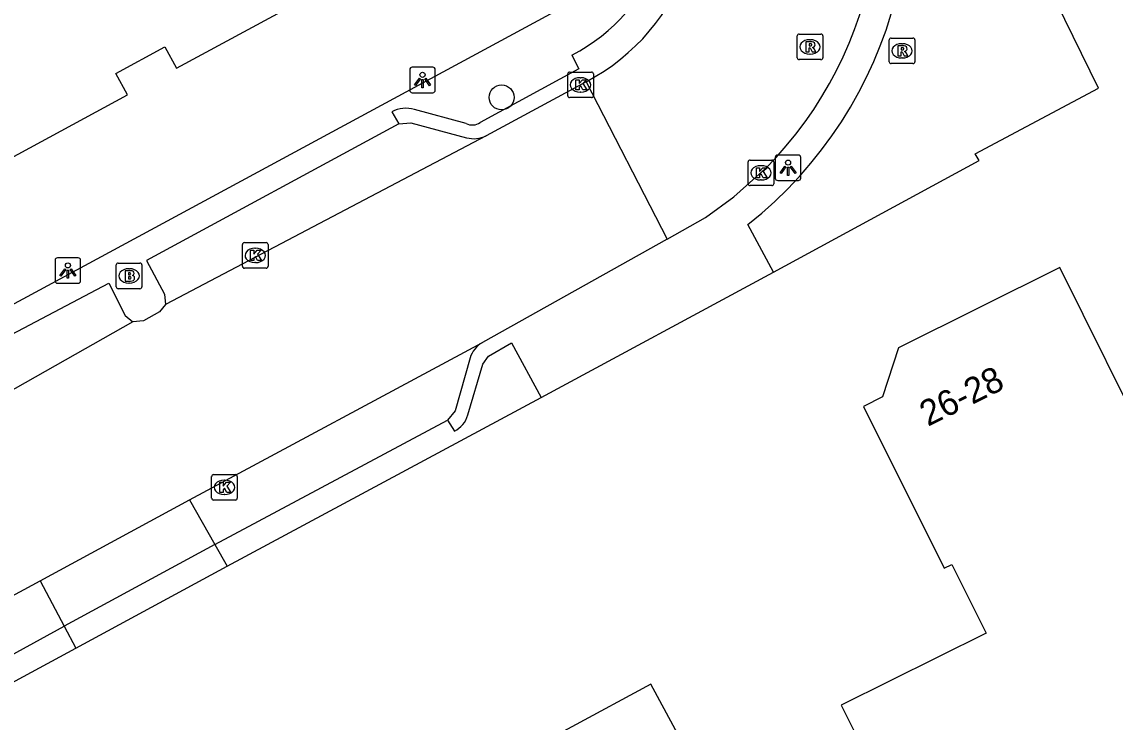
# Model space of a CAD drawing. Extents: x 158461 to 159795, y 387220 to 388672.
# Drawn here: x 158920.02 to 158962.78, y 387554.14 to 387581.53 of the extents above; entities that cross this region are included whole.
import ezdxf

# ---------------------------------------------------------------- set-up
doc = ezdxf.new("R2010")
doc.units = 0
for name, color, linetype in [('IMGEO_Boom', 7, 'Continuous'), ('IMGEO_Brandkraan', 7, 'Continuous'), ('IMGEO_Kolk', 7, 'Continuous'), ('IMGEO_Lichtpunt', 7, 'Continuous'), ('IMGEO_Pand', 7, 'Continuous'), ('IMGEO_Pand_nummerreeks', 7, 'Continuous'), ('IMGEO_Rijbaan_lokaal_gesloten', 7, 'Continuous'), ('IMGEO_Rioolput', 7, 'Continuous'), ('IMGEO_Voetpad_open', 7, 'Continuous')]:
    doc.layers.add(name, color=color, linetype=linetype)

msp = doc.modelspace()

# ---------------------------------------------------------------- linework, layer by layer
at = {"layer": 'IMGEO_Boom'}
msp.add_circle((158938.784, 387578.571), 0.489, dxfattribs=at)
at = {"layer": 'IMGEO_Brandkraan'}
for p, q in [((158923.79, 387572.09), (158924.642, 387572.09)), ((158923.715, 387571.164), (158923.715, 387572.016)), ((158924.203, 387571.87), (158924.228, 387571.87)), ((158924.716, 387572.016), (158924.716, 387571.164)), ((158924.226, 387571.31), (158924.201, 387571.31)), ((158924.642, 387571.09), (158923.79, 387571.09))]:
    msp.add_line(p, q, dxfattribs=at)
for points in [[(158923.79, 387572.09), (158924.642, 387572.09)], [(158923.715, 387571.164), (158923.715, 387572.016)], [(158924.063, 387571.79), (158924.063, 387571.39), (158924.276, 387571.39)], [(158924.294, 387571.79), (158924.063, 387571.79)], [(158924.242, 387571.709), (158924.188, 387571.709), (158924.188, 387571.633)], [(158924.716, 387572.016), (158924.716, 387571.164)], [(158924.188, 387571.633), (158924.241, 387571.633)], [(158924.25, 387571.557), (158924.188, 387571.557), (158924.188, 387571.476)], [(158924.188, 387571.476), (158924.25, 387571.476)], [(158924.642, 387571.09), (158923.79, 387571.09)]]:
    msp.add_lwpolyline(points, dxfattribs=at)
for centre, radius, start, end in [((158923.792, 387572.014), 0.0765, 91.552, 178.448), ((158923.792, 387572.014), 0.0765, 91.552, 178.448), ((158924.64, 387572.014), 0.0765, 1.552, 88.448), ((158924.64, 387572.014), 0.0765, 1.552, 88.448), ((158924.243, 387571.671), 0.0379, 267.8285, 90.9355), ((158924.298, 387571.645), 0.145, 59.4692, 91.5367), ((158924.323, 387571.692), 0.0922, 285.5137, 58.1501), ((158924.251, 387571.516), 0.0404, 269.8759, 90.5077), ((158924.282, 387571.641), 0.251, 268.6676, 293.5347), ((158924.328, 387571.5), 0.105, 301.3115, 78.989), ((158923.792, 387571.166), 0.0765, 181.552, 268.448), ((158923.792, 387571.166), 0.0765, 181.552, 268.448), ((158924.64, 387571.166), 0.0765, 271.552, 358.448), ((158924.64, 387571.166), 0.0765, 271.552, 358.448)]:
    msp.add_arc(centre, radius, start, end, dxfattribs=at)
for centre, major_axis, ratio, start_param, end_param in [((158924.202, 387571.59), (-0.387, 0.002), 0.722429, 4.712389, 7.853982), ((158924.227, 387571.59), (-0.39, 0.002), 0.717154, 1.570796, 4.712389)]:
    msp.add_ellipse(centre, major_axis=major_axis, ratio=ratio, start_param=start_param, end_param=end_param, dxfattribs=at)
at = {"layer": 'IMGEO_Kolk'}
for p, q in [((158941.371, 387578.635), (158941.371, 387579.487)), ((158941.446, 387579.561), (158942.298, 387579.561)), ((158942.372, 387579.487), (158942.372, 387578.635)), ((158941.859, 387579.341), (158941.884, 387579.341)), ((158942.298, 387578.561), (158941.446, 387578.561)), ((158941.882, 387578.781), (158941.857, 387578.781)), ((158948.426, 387575.195), (158948.426, 387576.047)), ((158948.501, 387576.121), (158949.353, 387576.121)), ((158949.427, 387576.047), (158949.427, 387575.195)), ((158948.914, 387575.901), (158948.939, 387575.901)), ((158949.353, 387575.121), (158948.501, 387575.121)), ((158948.937, 387575.341), (158948.912, 387575.341)), ((158928.649, 387571.964), (158928.649, 387572.816)), ((158928.724, 387572.89), (158929.576, 387572.89)), ((158929.137, 387572.67), (158929.162, 387572.67)), ((158929.65, 387572.816), (158929.65, 387571.964)), ((158929.16, 387572.11), (158929.135, 387572.11)), ((158929.576, 387571.89), (158928.724, 387571.89)), ((158927.445, 387562.895), (158927.445, 387563.747)), ((158927.52, 387563.821), (158928.372, 387563.821)), ((158927.933, 387563.601), (158927.958, 387563.601)), ((158928.446, 387563.747), (158928.446, 387562.895)), ((158928.372, 387562.821), (158927.52, 387562.821)), ((158927.956, 387563.041), (158927.931, 387563.041))]:
    msp.add_line(p, q, dxfattribs=at)
for points in [[(158941.371, 387578.635), (158941.371, 387579.487)], [(158941.446, 387579.561), (158942.298, 387579.561)], [(158942.372, 387579.487), (158942.372, 387578.635)], [(158941.692, 387579.261), (158941.815, 387579.261), (158941.815, 387579.11), (158941.945, 387579.261), (158942.109, 387579.261), (158941.963, 387579.11), (158942.116, 387578.861), (158941.964, 387578.861), (158941.879, 387579.025), (158941.815, 387578.958), (158941.815, 387578.861), (158941.692, 387578.861), (158941.692, 387579.261)], [(158942.298, 387578.561), (158941.446, 387578.561)], [(158948.426, 387575.195), (158948.426, 387576.047)], [(158948.501, 387576.121), (158949.353, 387576.121)], [(158949.427, 387576.047), (158949.427, 387575.195)], [(158948.747, 387575.821), (158948.87, 387575.821), (158948.87, 387575.67), (158949, 387575.821), (158949.164, 387575.821), (158949.018, 387575.67), (158949.171, 387575.421), (158949.019, 387575.421), (158948.934, 387575.585), (158948.87, 387575.518), (158948.87, 387575.421), (158948.747, 387575.421), (158948.747, 387575.821)], [(158949.353, 387575.121), (158948.501, 387575.121)], [(158928.649, 387571.964), (158928.649, 387572.816)], [(158928.724, 387572.89), (158929.576, 387572.89)], [(158928.97, 387572.59), (158929.093, 387572.59), (158929.093, 387572.439), (158929.223, 387572.59), (158929.387, 387572.59), (158929.241, 387572.439), (158929.394, 387572.19), (158929.242, 387572.19), (158929.157, 387572.354), (158929.093, 387572.287), (158929.093, 387572.19), (158928.97, 387572.19), (158928.97, 387572.59)], [(158929.65, 387572.816), (158929.65, 387571.964)], [(158929.576, 387571.89), (158928.724, 387571.89)], [(158927.445, 387562.895), (158927.445, 387563.747)], [(158927.52, 387563.821), (158928.372, 387563.821)], [(158928.446, 387563.747), (158928.446, 387562.895)], [(158927.766, 387563.521), (158927.889, 387563.521), (158927.889, 387563.37), (158928.019, 387563.521), (158928.183, 387563.521), (158928.037, 387563.37), (158928.19, 387563.121), (158928.038, 387563.121), (158927.953, 387563.285), (158927.889, 387563.218), (158927.889, 387563.121), (158927.766, 387563.121), (158927.766, 387563.521)], [(158928.372, 387562.821), (158927.52, 387562.821)]]:
    msp.add_lwpolyline(points, dxfattribs=at)
for centre, start, end in [((158941.448, 387579.485), 91.552, 178.448), ((158941.448, 387579.485), 91.552, 178.448), ((158942.296, 387579.485), 1.552, 88.448), ((158942.296, 387579.485), 1.552, 88.448), ((158941.448, 387578.637), 181.552, 268.448), ((158941.448, 387578.637), 181.552, 268.448), ((158942.296, 387578.637), 271.552, 358.448), ((158942.296, 387578.637), 271.552, 358.448), ((158948.503, 387576.045), 91.552, 178.448), ((158948.503, 387576.045), 91.552, 178.448), ((158949.351, 387576.045), 1.552, 88.448), ((158949.351, 387576.045), 1.552, 88.448), ((158948.503, 387575.197), 181.552, 268.448), ((158948.503, 387575.197), 181.552, 268.448), ((158949.351, 387575.197), 271.552, 358.448), ((158949.351, 387575.197), 271.552, 358.448), ((158928.726, 387572.814), 91.552, 178.448), ((158928.726, 387572.814), 91.552, 178.448), ((158929.574, 387572.814), 1.552, 88.448), ((158929.574, 387572.814), 1.552, 88.448), ((158928.726, 387571.966), 181.552, 268.448), ((158928.726, 387571.966), 181.552, 268.448), ((158929.574, 387571.966), 271.552, 358.448), ((158929.574, 387571.966), 271.552, 358.448), ((158927.522, 387563.745), 91.552, 178.448), ((158927.522, 387563.745), 91.552, 178.448), ((158928.37, 387563.745), 1.552, 88.448), ((158928.37, 387563.745), 1.552, 88.448), ((158927.522, 387562.897), 181.552, 268.448), ((158927.522, 387562.897), 181.552, 268.448), ((158928.37, 387562.897), 271.552, 358.448), ((158928.37, 387562.897), 271.552, 358.448)]:
    msp.add_arc(centre, 0.0765, start, end, dxfattribs=at)
for centre, major_axis, ratio, start_param, end_param in [((158941.858, 387579.061), (-0.387, 0.002), 0.722429, 4.712389, 7.853982), ((158941.883, 387579.061), (-0.39, 0.002), 0.717154, 1.570796, 4.712389), ((158948.913, 387575.621), (-0.387, 0.002), 0.722429, 4.712389, 7.853982), ((158948.938, 387575.621), (-0.39, 0.002), 0.717154, 1.570796, 4.712389), ((158929.136, 387572.39), (-0.387, 0.002), 0.722429, 4.712389, 7.853982), ((158929.161, 387572.39), (-0.39, 0.002), 0.717154, 1.570796, 4.712389), ((158927.932, 387563.321), (-0.387, 0.002), 0.722429, 4.712389, 7.853982), ((158927.957, 387563.321), (-0.39, 0.002), 0.717154, 1.570796, 4.712389)]:
    msp.add_ellipse(centre, major_axis=major_axis, ratio=ratio, start_param=start_param, end_param=end_param, dxfattribs=at)
at = {"layer": 'IMGEO_Lichtpunt'}
for p, q in [((158935.193, 387579.656), (158935.193, 387578.849)), ((158935.193, 387579.656), (158935.193, 387578.849)), ((158936.095, 387579.751), (158935.287, 387579.751)), ((158936.095, 387579.751), (158935.287, 387579.751)), ((158936.189, 387578.849), (158936.189, 387579.656)), ((158936.189, 387578.849), (158936.189, 387579.656)), ((158935.287, 387578.755), (158936.095, 387578.755)), ((158935.287, 387578.755), (158936.095, 387578.755)), ((158949.488, 387576.223), (158949.488, 387575.416)), ((158949.488, 387576.223), (158949.488, 387575.416)), ((158950.39, 387576.318), (158949.582, 387576.318)), ((158950.39, 387576.318), (158949.582, 387576.318)), ((158950.484, 387575.416), (158950.484, 387576.223)), ((158950.484, 387575.416), (158950.484, 387576.223)), ((158949.582, 387575.322), (158950.39, 387575.322)), ((158949.582, 387575.322), (158950.39, 387575.322)), ((158921.324, 387572.201), (158921.324, 387571.394)), ((158921.324, 387572.201), (158921.324, 387571.394)), ((158922.226, 387572.296), (158921.418, 387572.296)), ((158922.226, 387572.296), (158921.418, 387572.296)), ((158922.32, 387571.394), (158922.32, 387572.201)), ((158922.32, 387571.394), (158922.32, 387572.201)), ((158921.418, 387571.3), (158922.226, 387571.3)), ((158921.418, 387571.3), (158922.226, 387571.3))]:
    msp.add_line(p, q, dxfattribs=at)
for points in [[(158935.567, 387579.32), (158935.606, 387579.292), (158935.418, 387579.03), (158935.38, 387579.057), (158935.567, 387579.32)], [(158935.669, 387579.272), (158935.716, 387579.272), (158935.716, 387578.95), (158935.669, 387578.95), (158935.669, 387579.272)], [(158935.779, 387579.292), (158935.817, 387579.319), (158936.004, 387579.057), (158935.965, 387579.029), (158935.779, 387579.292)], [(158949.862, 387575.887), (158949.901, 387575.859), (158949.713, 387575.597), (158949.675, 387575.624), (158949.862, 387575.887)], [(158949.964, 387575.839), (158950.011, 387575.839), (158950.011, 387575.517), (158949.964, 387575.517), (158949.964, 387575.839)], [(158950.074, 387575.859), (158950.112, 387575.886), (158950.299, 387575.624), (158950.26, 387575.596), (158950.074, 387575.859)], [(158921.698, 387571.865), (158921.737, 387571.837), (158921.549, 387571.575), (158921.511, 387571.602), (158921.698, 387571.865)], [(158921.8, 387571.817), (158921.847, 387571.817), (158921.847, 387571.495), (158921.8, 387571.495), (158921.8, 387571.817)], [(158921.91, 387571.837), (158921.948, 387571.864), (158922.135, 387571.602), (158922.096, 387571.574), (158921.91, 387571.837)]]:
    msp.add_lwpolyline(points, dxfattribs=at)
for centre in [(158935.692, 387579.454), (158949.987, 387576.021), (158921.823, 387571.999)]:
    msp.add_circle(centre, 0.0994, dxfattribs=at)
for centre, start, end in [((158935.287, 387579.656), 90, 180), ((158935.287, 387579.656), 90, 180), ((158936.095, 387579.656), 0, 90), ((158936.095, 387579.656), 0, 90), ((158935.287, 387578.849), 180, 270), ((158935.287, 387578.849), 180, 270), ((158936.095, 387578.849), 270, 0), ((158936.095, 387578.849), 270, 360), ((158949.582, 387576.223), 90, 180), ((158949.582, 387576.223), 90, 180), ((158950.39, 387576.223), 0, 90), ((158950.39, 387576.223), 0, 90), ((158949.582, 387575.416), 180, 270), ((158949.582, 387575.416), 180, 270), ((158950.39, 387575.416), 270, 0), ((158950.39, 387575.416), 270, 360), ((158921.418, 387572.201), 90, 180), ((158921.418, 387572.201), 90, 180), ((158922.226, 387572.201), 0, 90), ((158922.226, 387572.201), 0, 90), ((158921.418, 387571.394), 180, 270), ((158921.418, 387571.394), 180, 270), ((158922.226, 387571.394), 270, 0), ((158922.226, 387571.394), 270, 360)]:
    msp.add_arc(centre, 0.0946, start, end, dxfattribs=at)
at = {"layer": 'IMGEO_Pand'}
for points in [[(158914.699, 387602.452), (158910.485, 387600.359), (158915.311, 387590.485), (158915.891, 387590.799), (158918.705, 387584.828), (158912.764, 387581.761), (158912.483, 387582.336), (158909.259, 387580.614), (158911.073, 387577.264), (158913.453, 387572.866), (158924.16, 387578.666), (158923.703, 387579.511), (158925.617, 387580.555), (158926.073, 387579.71), (158938.278, 387586.305), (158935.078, 387592.236), (158932.757, 387590.996), (158932.392, 387591.679)], [(158962.688, 387522.246), (158980.248, 387531.766), (158984.643, 387534.149), (158970.358, 387562.77), (158969.322, 387564.904), (158968.455, 387566.688), (158964.251, 387564.592), (158960.613, 387571.916), (158954.312, 387568.777), (158953.678, 387566.859), (158952.931, 387566.476), (158956.09, 387560.157), (158956.386, 387560.305), (158957.728, 387557.622), (158952.059, 387554.806), (158961.6, 387535.718), (158956.691, 387533.271)], [(158956.691, 387533.271), (158944.623, 387555.621), (158938.442, 387552.28), (158938.894, 387551.445), (158936.397, 387550.104), (158935.945, 387550.939), (158935.479, 387550.673), (158936.668, 387548.492), (158932.278, 387546.114), (158934.656, 387541.716), (158944.167, 387524.127), (158939.76, 387521.739), (158944.753, 387512.524), (158962.688, 387522.246)]]:
    msp.add_lwpolyline(points, dxfattribs=at)
at = {"layer": 'IMGEO_Rijbaan_lokaal_gesloten'}
for points in [[(158942.09, 387579.183), (158938.179, 387577.074)], [(158942.09, 387579.183), (158945.261, 387573.028)], [(158938.179, 387577.074), (158925.645, 387570.477)], [(158945.261, 387573.028), (158946.764, 387573.87), (158947.87, 387574.681), (158949.099, 387575.785)], [(158945.261, 387573.028), (158938.034, 387568.981)], [(158925.645, 387570.477), (158925.408, 387570.184), (158924.776, 387569.835), (158924.362, 387569.798)], [(158924.362, 387569.798), (158917.496, 387565.904)], [(158926.582, 387562.826), (158938.034, 387568.981)], [(158920.733, 387559.66), (158926.582, 387562.826)], [(158909.82, 387553.755), (158920.733, 387559.66)]]:
    msp.add_lwpolyline(points, dxfattribs=at)
for centre, radius, start, end in [((158938.192, 387586.604), 15.363, 315.2303, 25.487), ((158938.183, 387586.599), 8.382, 297.7816, 23.3629)]:
    msp.add_arc(centre, radius, start, end, dxfattribs=at)
at = {"layer": 'IMGEO_Rioolput'}
for p, q in [((158950.346, 387580.121), (158950.346, 387580.973)), ((158950.421, 387581.047), (158951.273, 387581.047)), ((158950.834, 387580.827), (158950.859, 387580.827)), ((158951.347, 387580.973), (158951.347, 387580.121)), ((158953.944, 387579.966), (158953.944, 387580.818)), ((158954.019, 387580.892), (158954.871, 387580.892)), ((158954.432, 387580.672), (158954.457, 387580.672)), ((158954.945, 387580.818), (158954.945, 387579.966)), ((158950.857, 387580.267), (158950.832, 387580.267)), ((158951.273, 387580.047), (158950.421, 387580.047)), ((158954.871, 387579.892), (158954.019, 387579.892)), ((158954.455, 387580.112), (158954.43, 387580.112))]:
    msp.add_line(p, q, dxfattribs=at)
for points in [[(158950.346, 387580.121), (158950.346, 387580.973)], [(158950.421, 387581.047), (158951.273, 387581.047)], [(158950.935, 387580.745), (158950.683, 387580.747), (158950.683, 387580.347)], [(158950.861, 387580.666), (158950.807, 387580.666), (158950.807, 387580.585)], [(158951.347, 387580.973), (158951.347, 387580.121)], [(158953.944, 387579.966), (158953.944, 387580.818)], [(158954.019, 387580.892), (158954.871, 387580.892)], [(158954.945, 387580.818), (158954.945, 387579.966)], [(158950.683, 387580.347), (158950.807, 387580.347), (158950.807, 387580.509), (158950.818, 387580.509)], [(158950.807, 387580.585), (158950.859, 387580.585)], [(158950.865, 387580.48), (158950.936, 387580.347), (158951.076, 387580.347), (158951.011, 387580.473)], [(158954.533, 387580.59), (158954.281, 387580.592), (158954.281, 387580.192)], [(158954.281, 387580.192), (158954.405, 387580.192), (158954.405, 387580.354), (158954.416, 387580.354)], [(158954.459, 387580.511), (158954.405, 387580.511), (158954.405, 387580.43)], [(158954.405, 387580.43), (158954.457, 387580.43)], [(158954.463, 387580.325), (158954.534, 387580.192), (158954.674, 387580.192), (158954.609, 387580.318)], [(158951.273, 387580.047), (158950.421, 387580.047)], [(158954.871, 387579.892), (158954.019, 387579.892)]]:
    msp.add_lwpolyline(points, dxfattribs=at)
for centre, radius, start, end in [((158950.423, 387580.971), 0.0765, 91.552, 178.448), ((158950.423, 387580.971), 0.0765, 91.552, 178.448), ((158950.867, 387580.57), 0.0964, 77.0061, 93.1865), ((158950.881, 387580.627), 0.0378, 276.6634, 79.6772), ((158950.934, 387580.635), 0.109, 350.3612, 89.416), ((158951.271, 387580.971), 0.0765, 1.552, 88.448), ((158951.271, 387580.971), 0.0765, 1.552, 88.448), ((158954.021, 387580.816), 0.0765, 91.552, 178.448), ((158954.021, 387580.816), 0.0765, 91.552, 178.448), ((158954.869, 387580.816), 0.0765, 1.552, 88.448), ((158954.869, 387580.816), 0.0765, 1.552, 88.448), ((158950.817, 387580.456), 0.0533, 26.0293, 88.6989), ((158950.843, 387580.774), 0.19, 274.7715, 282.9687), ((158950.932, 387580.635), 0.112, 277.5842, 350.9817), ((158950.916, 387580.42), 0.108, 29.5134, 73.7905), ((158954.415, 387580.301), 0.0533, 26.0293, 88.6989), ((158954.441, 387580.619), 0.19, 274.7715, 282.9687), ((158954.465, 387580.415), 0.0964, 77.0061, 93.1865), ((158954.479, 387580.472), 0.0378, 276.6634, 79.6772), ((158954.532, 387580.48), 0.109, 350.3612, 89.416), ((158954.53, 387580.48), 0.112, 277.5842, 350.9817), ((158954.514, 387580.265), 0.108, 29.5134, 73.7905), ((158950.423, 387580.123), 0.0765, 181.552, 268.448), ((158950.423, 387580.123), 0.0765, 181.552, 268.448), ((158951.271, 387580.123), 0.0765, 271.552, 358.448), ((158951.271, 387580.123), 0.0765, 271.552, 358.448), ((158954.021, 387579.968), 0.0765, 181.552, 268.448), ((158954.021, 387579.968), 0.0765, 181.552, 268.448), ((158954.869, 387579.968), 0.0765, 271.552, 358.448), ((158954.869, 387579.968), 0.0765, 271.552, 358.448)]:
    msp.add_arc(centre, radius, start, end, dxfattribs=at)
for centre, major_axis, ratio, start_param, end_param in [((158950.833, 387580.547), (-0.387, 0.002), 0.722429, 4.712389, 7.853982), ((158950.858, 387580.547), (-0.39, 0.002), 0.717154, 1.570796, 4.712389), ((158954.431, 387580.392), (-0.387, 0.002), 0.722429, 4.712389, 7.853982), ((158954.456, 387580.392), (-0.39, 0.002), 0.717154, 1.570796, 4.712389)]:
    msp.add_ellipse(centre, major_axis=major_axis, ratio=ratio, start_param=start_param, end_param=end_param, dxfattribs=at)
at = {"layer": 'IMGEO_Voetpad_open'}
for points in [[(158949.423, 387571.741), (158957.461, 387576.099), (158957.303, 387576.367), (158962.13, 387578.938), (158947.594, 387608.591), (158947.378, 387608.501), (158945.355, 387612.535)], [(158916.03, 387568.516), (158941.178, 387582.1)], [(158941.534, 387580.228), (158941.81, 387579.688), (158937.946, 387577.583)], [(158937.395, 387577.553), (158935.377, 387578.102)], [(158934.492, 387578.005), (158934.768, 387577.539)], [(158934.768, 387577.539), (158924.899, 387572.192), (158925.601, 387570.876), (158925.645, 387570.477)], [(158934.768, 387577.539), (158935.234, 387577.57), (158937.412, 387576.993)], [(158949.423, 387571.741), (158948.418, 387573.599)], [(158940.337, 387566.834), (158949.423, 387571.741)], [(158916.516, 387567.671), (158923.428, 387571.303), (158924.058, 387570.045), (158924.362, 387569.798)], [(158937.463, 387566.15), (158938.052, 387568.136), (158938.266, 387568.45), (158939.168, 387568.967), (158940.337, 387566.834)], [(158937.553, 387568.382), (158936.965, 387566.315), (158936.67, 387565.944)], [(158928.053, 387560.231), (158940.337, 387566.834)], [(158927.57, 387561.08), (158936.67, 387565.944)], [(158936.67, 387565.944), (158936.937, 387565.514)], [(158926.582, 387562.826), (158927.57, 387561.08)], [(158927.57, 387561.08), (158921.674, 387557.885)], [(158927.57, 387561.08), (158928.053, 387560.231)], [(158922.139, 387557.033), (158928.053, 387560.231)], [(158920.733, 387559.66), (158921.674, 387557.885)], [(158917.958, 387555.862), (158921.674, 387557.885)], [(158921.674, 387557.885), (158922.139, 387557.033)], [(158911.263, 387551.149), (158922.139, 387557.033)]]:
    msp.add_lwpolyline(points, dxfattribs=at)
for centre, radius, start, end in [((158938.075, 387586.665), 16.665, 308.3663, 22.5141), ((158938.27, 387586.568), 7.131, 297.2436, 23.0151), ((158935.058, 387576.923), 1.221, 74.8733, 117.6365), ((158937.645, 387578.036), 0.544, 242.6502, 303.5827), ((158937.691, 387578.026), 1.07, 254.908, 297.1489), ((158938.513, 387568.104), 0.999, 118.6331, 163.8376), ((158936.463, 387566.441), 1.041, 297.0568, 343.7587)]:
    msp.add_arc(centre, radius, start, end, dxfattribs=at)

# ---------------------------------------------------------------- texts
at = {"layer": 'IMGEO_Pand_nummerreeks'}
msp.add_text('26-28', height=1, rotation=26.4797, dxfattribs=at).set_placement((158955.456, 387565.683))

doc.saveas('drawing.dxf')
